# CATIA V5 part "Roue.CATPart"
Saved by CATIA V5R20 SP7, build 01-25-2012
Part number: Roue
Bounding box of the stored display mesh (mm): x -21 to 21, y -21 to 21, z 0 to 37.5
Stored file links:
  F:\Travaux\Modélisations\CFAO_2011\MMS\MMS_GR1\AA_OK\bmadec\Catia\Roue.CATPart
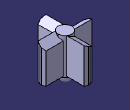
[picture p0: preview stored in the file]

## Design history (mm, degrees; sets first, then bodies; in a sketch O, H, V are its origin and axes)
Set1
  Plane1: type Offset, RefPlane zx-plane, Offset 21
Body1 (main body)
  Sketch1 on xy-plane, origin (0, 0, 0), H (1, 0, 0), V (0, 1, 0)
    circle A1 centre (0, 0) radius 6
    radius A1 = 6
  Pad1: profile Sketch1, direction (0, 0, 1), length 37.5
  Fillet1: radius 6, on edge [start face of Pad1 | face of Pad1 from Sketch1.A1]
  Sketch2 on Plane1, origin (0, 21, 0), H (-1, 0, 0), V (0, 0, 1)
    point P1 (-3.475, 37.5)
    line L1 (-3.475, 37.5) -> (-3.475, 7)
    line L2 (-3.475, 7) -> (3.475, 7)
    line L3 (3.475, 7) -> (3.475, 33.4874)
    line L4 (3.475, 33.4874) -> (-3.475, 37.5)
    reference projected line E1 (-6, 37.5) -> (6, 37.5) from edge [face of Pad1 from Sketch1.A1 | end face of Pad1]
    reference projected line E2 (-6, 6) -> (6, 6) from edge [face of Fillet1 | face of Pad1 from Sketch1.A1]
    angle L4 L1 = 60
    distance L2 E2 = 1
    length L2 = 6.95
    vertical: L1 V, L3 V
    horizontal: L2 H
    symmetry: L1 L3 V
    coincidence: P1 E1
  Pad2: profile Sketch2, direction (0, 1, 0), up to face of Pad1 from Sketch1.A1
  CircPattern1: of Pad2, instances 4, angular step 90, axis from face of Pad1 from Sketch1.A1
  Chamfer1: length 1, angle 70, on edge [face of Pad2 from Sketch2.L1 | start face of Pad2]; edge [face of Pad2 from Sketch2.L3 | start face of Pad2]; edge [face of CircPattern1 | face of CircPattern1] (x6)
